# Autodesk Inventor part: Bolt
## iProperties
Created: 2006-04
Part Number: Bolt
Document SubType Name: Modeling
Designer: Калинин
Author: Калинин
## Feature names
1. Вращение1 [Revolution]
2. Отверстие1 [Hole]
3. Отверстие2 [Hole]
4. Отверстие3 [Hole]
5. Вращение2 [Revolution]
6. Выдавливание1 [Extrusion]
7. Выдавливание2 [Extrusion]
8. Выдавливание3 [Extrusion]
9. Сдвиг1
10. Сопряжение1 [Fillet]
11. Сопряжение2 [Fillet]
12. Выдавливание4 [Extrusion]
13. Вращение3 [Revolution]
